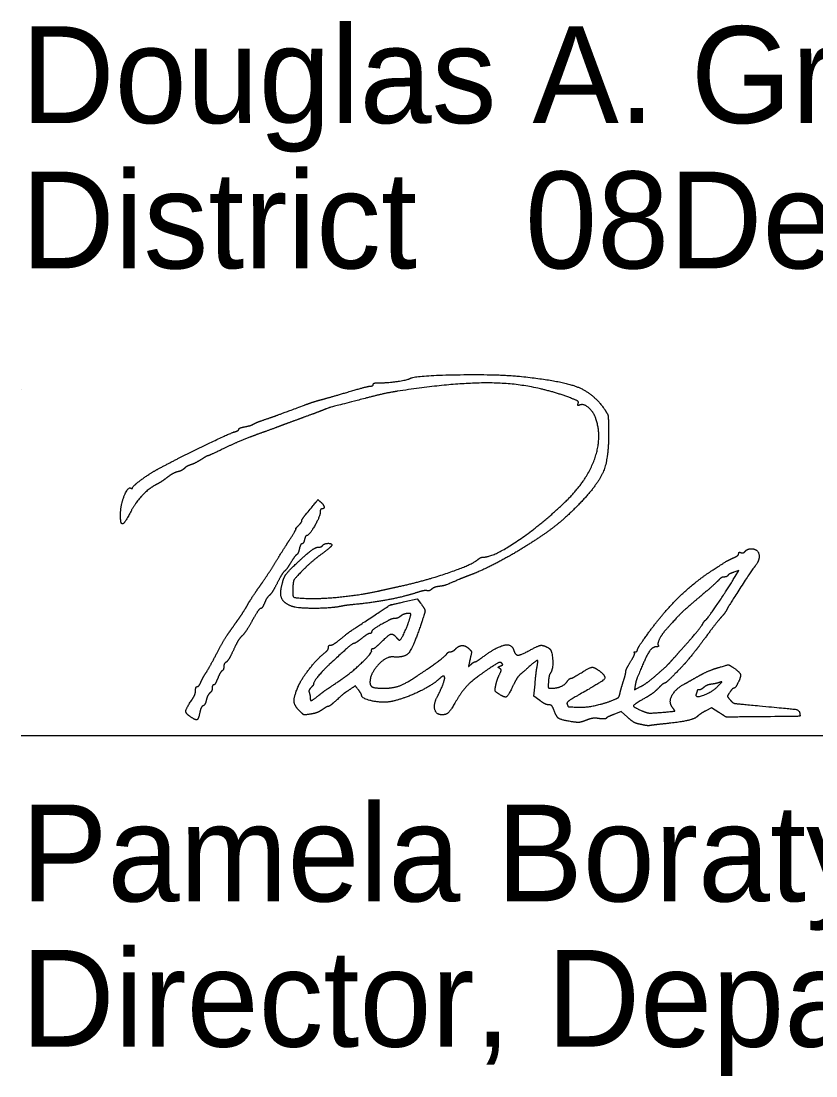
# Model space of a CAD drawing. Extents: x 0 to 34, y 0 to 22.
# Drawn here: x 24.5 to 25.648, y 7.199 to 8.723 of the extents above; entities that cross this region are included whole.
import ezdxf

# ---------------------------------------------------------------- set-up
doc = ezdxf.new("R2010")
doc.units = 0
doc.layers.add('SH_Data', color=7, linetype='Continuous')
doc.layers.add('SH_Text', color=7, linetype='Continuous')

msp = doc.modelspace()

# ---------------------------------------------------------------- linework, layer by layer
at = {"layer": 'SH_Data'}
for p, q in [((24.5, 8.191), (24.5, 8.191)), ((24.5, 7.691), (28, 7.691))]:
    msp.add_line(p, q, dxfattribs=at)
at = {"layer": 'SH_Text'}
for points in [[(25.5318, 7.9205), (25.5372, 7.9294), (25.5298, 7.9268)], [(25.0545, 7.8843), (25.0725, 7.8883), (25.0772, 7.8822)], [(25.2494, 7.7415), (25.2411, 7.7478), (25.2426, 7.7649)], [(25.3874, 7.7635), (25.3864, 7.757), (25.3951, 7.7614)], [(25.5083, 7.7242), (25.4976, 7.731), (25.4892, 7.7264)], [(25.3764, 7.7172), (25.3672, 7.7254), (25.3567, 7.7214)]]:
    msp.add_lwpolyline(points, dxfattribs=at)
for points in [[(25.0179, 8.2007), (25.0275, 8.2004), (25.0585, 8.2047), (25.0619, 8.2069)], [(25.0619, 8.2069), (25.0687, 8.2111), (25.1857, 8.2134), (25.2201, 8.21)], [(25.2201, 8.21), (25.2794, 8.2041), (25.3269, 8.1858), (25.3427, 8.1628)], [(24.9721, 8.1873), (24.9882, 8.192), (25.0031, 8.1959), (25.0051, 8.1959)], [(25.0437, 8.1884), (25.0345, 8.187), (25.0145, 8.1827), (24.9993, 8.1787)], [(25.0051, 8.1959), (25.0072, 8.1959), (25.0089, 8.1971), (25.0089, 8.1984)], [(25.0089, 8.1984), (25.0089, 8.1998), (25.0129, 8.2008), (25.0179, 8.2007)], [(25.2926, 8.1792), (25.242, 8.1982), (25.1341, 8.2022), (25.0437, 8.1884)], [(24.9093, 8.1683), (24.9172, 8.1713), (24.928, 8.1748), (24.9333, 8.1761)], [(24.9333, 8.1761), (24.9386, 8.1775), (24.9561, 8.1825), (24.9721, 8.1873)], [(24.9993, 8.1787), (24.9483, 8.1655), (24.944, 8.1643), (24.9333, 8.1599)], [(25.3049, 8.1706), (25.3059, 8.1731), (25.3024, 8.1755), (25.2926, 8.1792)], [(24.8529, 8.1477), (24.8676, 8.1528), (24.8741, 8.1552), (24.9093, 8.1683)], [(24.9333, 8.1599), (24.9307, 8.1589), (24.9204, 8.1551), (24.9105, 8.1515)], [(25.3073, 8.1685), (25.3047, 8.1675), (25.304, 8.1682), (25.3049, 8.1706)], [(25.3307, 8.1486), (25.3274, 8.1584), (25.313, 8.1707), (25.3073, 8.1685)], [(25.3427, 8.1628), (25.3476, 8.1555), (25.3486, 8.1512), (25.3489, 8.1333)], [(24.8349, 8.1405), (24.8362, 8.1415), (24.8443, 8.1448), (24.8529, 8.1477)], [(24.9105, 8.1515), (24.9006, 8.1479), (24.8855, 8.1423), (24.8769, 8.1391)], [(25.2852, 8.0274), (25.3161, 8.0568), (25.34, 8.1204), (25.3307, 8.1486)], [(24.6969, 8.0755), (24.7271, 8.0918), (24.8007, 8.1274), (24.8091, 8.1299)], [(24.8091, 8.1299), (24.8121, 8.1308), (24.8145, 8.1324), (24.8145, 8.1334)], [(24.8145, 8.1334), (24.8145, 8.1345), (24.8185, 8.1362), (24.8235, 8.1371)], [(24.8235, 8.1371), (24.8284, 8.138), (24.8336, 8.1396), (24.8349, 8.1405)], [(24.8769, 8.1391), (24.8683, 8.1358), (24.8521, 8.1299), (24.8409, 8.1259)], [(25.3489, 8.1333), (25.3496, 8.0926), (25.3335, 8.0529), (25.3041, 8.023)], [(24.8409, 8.1259), (24.8297, 8.1219), (24.8093, 8.1134), (24.7957, 8.1069)], [(24.7957, 8.1069), (24.782, 8.1004), (24.7704, 8.0951), (24.7698, 8.0951)], [(24.745, 8.082), (24.7418, 8.0809), (24.7376, 8.0786), (24.7358, 8.0768)], [(24.7598, 8.0895), (24.7549, 8.0864), (24.7482, 8.083), (24.745, 8.082)], [(24.7698, 8.0951), (24.7693, 8.0951), (24.7648, 8.0926), (24.7598, 8.0895)], [(24.6609, 8.0489), (24.6609, 8.0511), (24.6863, 8.0698), (24.6969, 8.0755)], [(24.7261, 8.072), (24.7226, 8.0711), (24.7159, 8.0675), (24.7113, 8.0639)], [(24.7358, 8.0768), (24.734, 8.075), (24.7297, 8.0728), (24.7261, 8.072)], [(24.6954, 8.0536), (24.685, 8.0482), (24.6651, 8.0274), (24.6589, 8.0153)], [(24.7113, 8.0639), (24.7067, 8.0603), (24.6995, 8.0557), (24.6954, 8.0536)], [(24.6437, 8.0111), (24.6438, 8.0242), (24.6545, 8.0508), (24.6586, 8.0483)], [(24.6586, 8.0483), (24.6599, 8.0475), (24.6609, 8.0478), (24.6609, 8.0489)], [(24.9111, 8.01), (24.9296, 8.0321), (24.9289, 8.0316), (24.933, 8.0282)], [(24.933, 8.0282), (24.9373, 8.0246), (24.9382, 8.0183), (24.9345, 8.0183)], [(25.1685, 7.9487), (25.1826, 7.9487), (25.2507, 7.9946), (25.2852, 8.0274)], [(25.3041, 8.023), (25.2855, 8.0041), (25.2531, 7.9792), (25.2226, 7.9603)], [(24.6451, 7.9973), (24.6443, 7.9981), (24.6437, 8.0043), (24.6437, 8.0111)], [(24.6589, 8.0153), (24.6522, 8.0024), (24.6469, 7.9955), (24.6451, 7.9973)], [(24.9057, 8.0013), (24.9057, 8.0025), (24.9081, 8.0064), (24.9111, 8.01)], [(24.9321, 8.0133), (24.9321, 8.0077), (24.9162, 7.9799), (24.913, 7.9799)], [(24.9345, 8.0183), (24.9332, 8.0183), (24.9321, 8.0161), (24.9321, 8.0133)], [(24.8881, 7.9739), (24.8937, 7.9825), (24.8977, 7.9895), (24.8971, 7.9895)], [(24.8971, 7.9895), (24.8966, 7.9895), (24.8983, 7.9917), (24.9009, 7.9943)], [(24.9009, 7.9943), (24.9035, 7.997), (24.9057, 8.0001), (24.9057, 8.0013)], [(24.913, 7.9799), (24.9119, 7.9799), (24.9103, 7.9772), (24.9095, 7.9739)], [(24.8661, 7.9389), (24.8727, 7.9495), (24.8826, 7.9653), (24.8881, 7.9739)], [(24.8973, 7.939), (24.913, 7.9536), (24.9258, 7.9631), (24.9297, 7.9631)], [(24.9021, 7.9608), (24.9012, 7.9568), (24.8995, 7.953), (24.8982, 7.9522)], [(24.9058, 7.9679), (24.9047, 7.9679), (24.903, 7.9647), (24.9021, 7.9608)], [(24.9095, 7.9739), (24.9087, 7.9706), (24.907, 7.9679), (24.9058, 7.9679)], [(24.9297, 7.9631), (24.9322, 7.9631), (24.9349, 7.9642), (24.9357, 7.9655)], [(24.9489, 7.9659), (24.9489, 7.9648), (24.9421, 7.9589), (24.9339, 7.9528)], [(24.9357, 7.9655), (24.9375, 7.9684), (24.9489, 7.9688), (24.9489, 7.9659)], [(25.2226, 7.9603), (25.2035, 7.9485), (25.1622, 7.9275), (25.1481, 7.9224)], [(25.5466, 7.9573), (25.5482, 7.9592), (25.5519, 7.9607), (25.5548, 7.9607)], [(25.5548, 7.9607), (25.5643, 7.9607), (25.568, 7.9447), (25.5606, 7.9357)], [(24.8982, 7.9522), (24.8969, 7.9514), (24.8931, 7.9462), (24.8897, 7.9407)], [(24.9339, 7.9528), (24.9256, 7.9467), (24.9131, 7.9358), (24.9061, 7.9287)], [(25.0485, 7.9068), (25.0854, 7.915), (25.1517, 7.9379), (25.1603, 7.9454)], [(25.1603, 7.9454), (25.1624, 7.9472), (25.1661, 7.9487), (25.1685, 7.9487)], [(25.5001, 7.9304), (25.5191, 7.9426), (25.5209, 7.9437), (25.5291, 7.9474)], [(25.5291, 7.9474), (25.5334, 7.9493), (25.5369, 7.9521), (25.5369, 7.9537)], [(25.5369, 7.9537), (25.5369, 7.9552), (25.5384, 7.9559), (25.5403, 7.9551)], [(25.5403, 7.9551), (25.5422, 7.9544), (25.545, 7.9554), (25.5466, 7.9573)], [(24.8443, 7.9059), (24.8497, 7.9134), (24.8595, 7.9282), (24.8661, 7.9389)], [(24.876, 7.9043), (24.8787, 7.9174), (24.8849, 7.9274), (24.8973, 7.939)], [(24.8897, 7.9407), (24.8863, 7.9352), (24.8822, 7.9296), (24.8806, 7.9283)], [(24.9061, 7.9287), (24.8954, 7.9177), (24.8932, 7.914), (24.8927, 7.9058)], [(25.4055, 7.8378), (25.4278, 7.8686), (25.4728, 7.9127), (25.5001, 7.9304)], [(25.5606, 7.9357), (25.5564, 7.9307), (25.5236, 7.8802), (25.5204, 7.8741)], [(24.8806, 7.9283), (24.8789, 7.927), (24.8742, 7.9194), (24.8702, 7.9114)], [(25.1325, 7.9162), (25.1154, 7.9088), (25.1105, 7.9071), (25.1039, 7.9063)], [(25.1481, 7.9224), (25.1435, 7.9207), (25.1364, 7.918), (25.1325, 7.9162)], [(25.507, 7.9145), (25.5043, 7.9116), (25.4918, 7.9005), (25.4793, 7.89)], [(25.489, 7.8575), (25.4918, 7.8595), (25.52, 7.901), (25.5318, 7.9205)], [(25.5158, 7.9199), (25.5136, 7.9199), (25.5097, 7.9175), (25.507, 7.9145)], [(25.5212, 7.9221), (25.5204, 7.9209), (25.518, 7.9199), (25.5158, 7.9199)], [(25.5298, 7.9268), (25.5258, 7.9254), (25.5219, 7.9233), (25.5212, 7.9221)], [(24.8276, 7.8803), (24.8315, 7.8869), (24.839, 7.8985), (24.8443, 7.9059)], [(24.8702, 7.9114), (24.8662, 7.9034), (24.8611, 7.8954), (24.859, 7.8936)], [(24.8913, 7.8775), (24.8809, 7.8814), (24.8737, 7.8938), (24.876, 7.9043)], [(24.8927, 7.9058), (24.8918, 7.8923), (24.8959, 7.8895), (24.9165, 7.8889)], [(24.9165, 7.8889), (24.9358, 7.8884), (24.9936, 7.8945), (25.0149, 7.8993)], [(25.0149, 7.8993), (25.0228, 7.9011), (25.0379, 7.9045), (25.0485, 7.9068)], [(25.0863, 7.9001), (25.0846, 7.9007), (25.0765, 7.899), (25.0683, 7.8963)], [(25.0931, 7.9022), (25.091, 7.9004), (25.0879, 7.8995), (25.0863, 7.9001)], [(25.1039, 7.9063), (25.1, 7.9059), (25.0952, 7.9041), (25.0931, 7.9022)], [(24.859, 7.8936), (24.8568, 7.8918), (24.8535, 7.8867), (24.8517, 7.8823)], [(25.0683, 7.8963), (25.0518, 7.891), (25.0067, 7.8826), (24.9829, 7.8803)], [(25.0005, 7.8579), (25.0322, 7.8789), (25.0335, 7.8796), (25.0545, 7.8843)], [(25.4793, 7.89), (25.4597, 7.8734), (25.448, 7.862), (25.4313, 7.8432)], [(24.8146, 7.8597), (24.8179, 7.8645), (24.8238, 7.8737), (24.8276, 7.8803)], [(24.846, 7.8743), (24.8447, 7.8743), (24.8393, 7.8664), (24.8339, 7.8568)], [(24.8517, 7.8823), (24.8498, 7.8779), (24.8473, 7.8743), (24.846, 7.8743)], [(24.9625, 7.8776), (24.9488, 7.8746), (24.8993, 7.8745), (24.8913, 7.8775)], [(24.9829, 7.8803), (24.9746, 7.8795), (24.9654, 7.8783), (24.9625, 7.8776)], [(25.0772, 7.8822), (25.0838, 7.8734), (25.0836, 7.8685), (25.0759, 7.846)], [(25.5204, 7.8741), (25.5187, 7.8706), (25.5148, 7.8652), (25.5118, 7.8619)], [(24.801, 7.8405), (24.8051, 7.8463), (24.8112, 7.8549), (24.8146, 7.8597)], [(24.8339, 7.8568), (24.8286, 7.8471), (24.8219, 7.8371), (24.8191, 7.8346)], [(24.9613, 7.83), (24.975, 7.841), (24.973, 7.8396), (25.0005, 7.8579)], [(25.0302, 7.8568), (25.0158, 7.8489), (25.0065, 7.8425), (25.0065, 7.8405)], [(25.0399, 7.8599), (25.0377, 7.8599), (25.0333, 7.8585), (25.0302, 7.8568)], [(25.0486, 7.8635), (25.0461, 7.8615), (25.0421, 7.8599), (25.0399, 7.8599)], [(25.0471, 7.8287), (25.0489, 7.8287), (25.0587, 7.8499), (25.0618, 7.8605)], [(25.0585, 7.8671), (25.0557, 7.867), (25.0512, 7.8654), (25.0486, 7.8635)], [(25.0618, 7.8605), (25.0635, 7.8663), (25.0631, 7.8671), (25.0585, 7.8671)], [(25.4538, 7.8146), (25.4691, 7.8317), (25.4827, 7.8481), (25.4851, 7.8524)], [(25.4851, 7.8524), (25.4863, 7.8546), (25.4881, 7.8569), (25.489, 7.8575)], [(25.5118, 7.8619), (25.5088, 7.8587), (25.4999, 7.8474), (25.492, 7.8367)], [(24.7821, 7.8083), (24.7884, 7.8202), (24.7969, 7.8347), (24.801, 7.8405)], [(25.0038, 7.8383), (25.0024, 7.8383), (24.9971, 7.8351), (24.9921, 7.8311)], [(25.0065, 7.8405), (25.0065, 7.8393), (25.0053, 7.8383), (25.0038, 7.8383)], [(25.0209, 7.8263), (25.031, 7.8365), (25.0376, 7.8383), (25.0425, 7.8323)], [(25.0759, 7.846), (25.0656, 7.8161), (25.0537, 7.803), (25.0377, 7.8044)], [(25.3905, 7.8145), (25.3905, 7.8159), (25.3972, 7.8264), (25.4055, 7.8378)], [(25.4313, 7.8432), (25.4255, 7.8366), (25.4192, 7.8237), (25.4206, 7.8213)], [(24.8191, 7.8346), (24.8162, 7.832), (24.8107, 7.8229), (24.8068, 7.8143)], [(24.981, 7.8239), (24.9791, 7.8239), (24.9706, 7.8167), (24.9453, 7.7934)], [(24.9475, 7.8215), (24.9493, 7.8215), (24.9555, 7.8253), (24.9613, 7.83)], [(24.9921, 7.8311), (24.9871, 7.8272), (24.9821, 7.8239), (24.981, 7.8239)], [(25.0089, 7.8167), (25.0102, 7.8167), (25.0156, 7.8211), (25.0209, 7.8263)], [(25.0425, 7.8323), (25.0441, 7.8304), (25.0462, 7.8287), (25.0471, 7.8287)], [(25.1657, 7.8033), (25.1859, 7.8184), (25.2086, 7.824), (25.2116, 7.8146)], [(25.492, 7.8367), (25.4841, 7.8261), (25.4765, 7.8159), (25.475, 7.814)], [(24.7667, 7.7807), (24.7689, 7.784), (24.7759, 7.7965), (24.7821, 7.8083)], [(24.8068, 7.8143), (24.8029, 7.8058), (24.7981, 7.7979), (24.7963, 7.7968)], [(24.9006, 7.7621), (24.9051, 7.7725), (24.9283, 7.802), (24.9387, 7.8103)], [(24.9387, 7.8103), (24.9417, 7.8127), (24.9441, 7.8162), (24.9441, 7.8181)], [(24.9441, 7.8181), (24.9441, 7.82), (24.9456, 7.8215), (24.9475, 7.8215)], [(24.9604, 7.7702), (24.976, 7.7806), (25.0065, 7.8093), (25.0065, 7.8136)], [(25.0065, 7.8136), (25.0065, 7.8153), (25.0076, 7.8167), (25.0089, 7.8167)], [(25.0725, 7.7771), (25.0911, 7.7894), (25.1135, 7.8061), (25.1152, 7.8089)], [(25.1152, 7.8089), (25.1163, 7.8106), (25.1186, 7.8119), (25.1204, 7.8119)], [(25.1204, 7.8119), (25.1223, 7.8119), (25.1255, 7.8137), (25.1277, 7.8158)], [(25.1277, 7.8158), (25.1326, 7.8208), (25.1426, 7.8209), (25.1475, 7.8159)], [(25.1475, 7.8159), (25.1507, 7.8128), (25.1509, 7.8103), (25.1488, 7.8011)], [(25.2116, 7.8146), (25.214, 7.807), (25.2221, 7.8069), (25.2354, 7.8142)], [(25.2354, 7.8142), (25.2474, 7.8208), (25.2546, 7.8216), (25.2628, 7.817)], [(25.2628, 7.817), (25.2672, 7.8145), (25.2689, 7.7865), (25.265, 7.7813)], [(25.3807, 7.7976), (25.3846, 7.8039), (25.3871, 7.8097), (25.3863, 7.8105)], [(25.3863, 7.8105), (25.3855, 7.8113), (25.3862, 7.8119), (25.3877, 7.8119)], [(25.3877, 7.8119), (25.3892, 7.8119), (25.3905, 7.8131), (25.3905, 7.8145)], [(25.4184, 7.8191), (25.412, 7.8191), (25.4025, 7.804), (25.3904, 7.7747)], [(25.4206, 7.8213), (25.4214, 7.8201), (25.4204, 7.8191), (25.4184, 7.8191)], [(25.4382, 7.7971), (25.4413, 7.8006), (25.4484, 7.8085), (25.4538, 7.8146)], [(25.475, 7.814), (25.4617, 7.7976), (25.4572, 7.7925), (25.4453, 7.7803)], [(24.7963, 7.7968), (24.7944, 7.7958), (24.7929, 7.7929), (24.7929, 7.7904)], [(24.9453, 7.7934), (24.9362, 7.785), (24.9225, 7.768), (24.9225, 7.765)], [(25.0377, 7.8044), (25.0273, 7.8053), (25.0041, 7.7799), (25.0041, 7.7676)], [(25.1488, 7.8011), (25.1465, 7.7909), (25.1466, 7.7904), (25.1504, 7.7939)], [(25.1504, 7.7939), (25.1526, 7.7959), (25.1553, 7.7975), (25.1562, 7.7975)], [(25.1562, 7.7975), (25.1572, 7.7975), (25.1615, 7.8001), (25.1657, 7.8033)], [(25.1943, 7.7955), (25.1925, 7.7973), (25.1866, 7.7945), (25.1741, 7.786)], [(25.1915, 7.7878), (25.1893, 7.7892), (25.1896, 7.7901), (25.1927, 7.7913)], [(25.1927, 7.7913), (25.1957, 7.7924), (25.1962, 7.7936), (25.1943, 7.7955)], [(25.2354, 7.7914), (25.2195, 7.7774), (25.2158, 7.773), (25.2103, 7.7616)], [(25.2455, 7.7897), (25.2474, 7.7992), (25.2447, 7.7996), (25.2354, 7.7914)], [(25.3737, 7.7829), (25.3737, 7.7847), (25.3769, 7.7914), (25.3807, 7.7976)], [(25.4181, 7.7783), (25.426, 7.7851), (25.4351, 7.7936), (25.4382, 7.7971)], [(25.5074, 7.789), (25.5215, 7.7932), (25.5226, 7.7932), (25.5285, 7.7894)], [(24.7598, 7.7681), (24.7614, 7.7718), (24.7645, 7.7774), (24.7667, 7.7807)], [(24.7904, 7.7843), (24.789, 7.7834), (24.7862, 7.7785), (24.7841, 7.7733)], [(24.7929, 7.7904), (24.7929, 7.7879), (24.7918, 7.7851), (24.7904, 7.7843)], [(25.024, 7.7591), (25.0371, 7.7591), (25.0562, 7.7662), (25.0725, 7.7771)], [(25.1121, 7.7738), (25.1121, 7.7769), (25.1081, 7.7764), (25.1045, 7.7729)], [(25.1741, 7.786), (25.1544, 7.7726), (25.1372, 7.7555), (25.1289, 7.7411)], [(25.1857, 7.7623), (25.1865, 7.7665), (25.1888, 7.7736), (25.1908, 7.778)], [(25.1908, 7.778), (25.1937, 7.7842), (25.1938, 7.7864), (25.1915, 7.7878)], [(25.2426, 7.7649), (25.2434, 7.7743), (25.2447, 7.7854), (25.2455, 7.7897)], [(25.265, 7.7813), (25.2637, 7.7797), (25.2624, 7.774), (25.262, 7.7687)], [(25.2945, 7.7735), (25.2957, 7.7735), (25.3018, 7.7768), (25.3081, 7.7807)], [(25.3363, 7.7837), (25.346, 7.7761), (25.3391, 7.7682), (25.3076, 7.7505)], [(25.3081, 7.7807), (25.321, 7.789), (25.3286, 7.7898), (25.3363, 7.7837)], [(25.3702, 7.7687), (25.3721, 7.7747), (25.3737, 7.781), (25.3737, 7.7829)], [(25.3951, 7.7614), (25.3998, 7.7639), (25.4102, 7.7715), (25.4181, 7.7783)], [(25.4453, 7.7803), (25.4378, 7.7726), (25.4308, 7.7663), (25.4297, 7.7663)], [(25.4585, 7.7653), (25.4614, 7.7668), (25.4702, 7.7718), (25.4781, 7.7763)], [(25.4781, 7.7763), (25.486, 7.7808), (25.4992, 7.7865), (25.5074, 7.789)], [(25.5285, 7.7894), (25.5381, 7.7831), (25.5405, 7.7757), (25.5359, 7.7667)], [(24.7521, 7.7559), (24.7521, 7.759), (24.7532, 7.7615), (24.7545, 7.7615)], [(24.7545, 7.7615), (24.7559, 7.7615), (24.7583, 7.7645), (24.7598, 7.7681)], [(24.7782, 7.7639), (24.7771, 7.7639), (24.7761, 7.7619), (24.7761, 7.7594)], [(24.7841, 7.7733), (24.7821, 7.7682), (24.7794, 7.7639), (24.7782, 7.7639)], [(24.9023, 7.7264), (24.8947, 7.734), (24.8941, 7.7468), (24.9006, 7.7621)], [(24.9225, 7.765), (24.9225, 7.7642), (24.9208, 7.7619), (24.9188, 7.7599)], [(24.9289, 7.7478), (24.9364, 7.7539), (24.9417, 7.7576), (24.9604, 7.7702)], [(24.9875, 7.7566), (24.983, 7.7624), (24.983, 7.7624), (24.9762, 7.758)], [(25.0041, 7.7676), (25.0041, 7.7625), (25.0119, 7.7591), (25.024, 7.7591)], [(25.1045, 7.7729), (25.0949, 7.7638), (25.0562, 7.745), (25.0377, 7.7405)], [(25.1015, 7.7471), (25.1056, 7.7548), (25.1121, 7.7711), (25.1121, 7.7738)], [(25.1903, 7.7508), (25.1853, 7.7541), (25.1845, 7.7561), (25.1857, 7.7623)], [(25.2103, 7.7616), (25.2036, 7.7479), (25.1988, 7.7453), (25.1903, 7.7508)], [(25.262, 7.7687), (25.2615, 7.7612), (25.2622, 7.7591), (25.2654, 7.7591)], [(25.2654, 7.7591), (25.2737, 7.7591), (25.2857, 7.764), (25.289, 7.7687)], [(25.289, 7.7687), (25.2908, 7.7713), (25.2933, 7.7735), (25.2945, 7.7735)], [(25.3654, 7.7517), (25.3661, 7.7551), (25.3683, 7.7628), (25.3702, 7.7687)], [(25.3904, 7.7747), (25.3893, 7.7721), (25.388, 7.767), (25.3874, 7.7635)], [(25.4297, 7.7663), (25.4286, 7.7663), (25.4247, 7.7632), (25.4211, 7.7594)], [(25.4415, 7.7309), (25.4354, 7.7383), (25.4452, 7.7581), (25.4585, 7.7653)], [(25.4755, 7.751), (25.473, 7.7445), (25.4984, 7.7534), (25.5069, 7.7621)], [(25.4975, 7.7649), (25.4936, 7.7644), (25.4887, 7.7623), (25.4865, 7.7603)], [(25.5093, 7.7676), (25.5067, 7.7666), (25.5013, 7.7654), (25.4975, 7.7649)], [(25.5069, 7.7621), (25.5124, 7.7676), (25.513, 7.769), (25.5093, 7.7676)], [(25.5359, 7.7667), (25.5337, 7.7625), (25.531, 7.7591), (25.5299, 7.7591)], [(24.7463, 7.7416), (24.7495, 7.7464), (24.7521, 7.7528), (24.7521, 7.7559)], [(24.7727, 7.7521), (24.7708, 7.7505), (24.7685, 7.746), (24.7676, 7.742)], [(24.7761, 7.7594), (24.7761, 7.757), (24.7745, 7.7536), (24.7727, 7.7521)], [(24.9188, 7.7599), (24.9167, 7.7578), (24.9156, 7.7546), (24.9164, 7.7526)], [(24.9164, 7.7526), (24.9171, 7.7507), (24.9177, 7.7476), (24.9177, 7.7457)], [(24.9177, 7.7457), (24.9177, 7.7409), (24.9211, 7.7415), (24.9289, 7.7478)], [(24.9762, 7.758), (24.968, 7.7526), (24.9654, 7.7506), (24.9542, 7.7405)], [(24.992, 7.7492), (24.992, 7.75), (24.99, 7.7534), (24.9875, 7.7566)], [(25.0377, 7.7405), (25.0248, 7.7374), (24.9922, 7.7436), (24.992, 7.7492)], [(25.1082, 7.7207), (25.0998, 7.7207), (25.0958, 7.7365), (25.1015, 7.7471)], [(25.3076, 7.7505), (25.2943, 7.743), (25.2881, 7.7382), (25.289, 7.736)], [(25.3527, 7.741), (25.3615, 7.7444), (25.3645, 7.7469), (25.3654, 7.7517)], [(25.4031, 7.7458), (25.3852, 7.7354), (25.3842, 7.7321), (25.3971, 7.7266)], [(25.4211, 7.7594), (25.4175, 7.7556), (25.4094, 7.7494), (25.4031, 7.7458)], [(25.4769, 7.7557), (25.4769, 7.7552), (25.4763, 7.7531), (25.4755, 7.751)], [(25.4797, 7.7567), (25.4782, 7.7567), (25.4769, 7.7563), (25.4769, 7.7557)], [(25.4865, 7.7603), (25.4843, 7.7584), (25.4813, 7.7567), (25.4797, 7.7567)], [(25.524, 7.7533), (25.5205, 7.748), (25.5206, 7.7471), (25.5244, 7.7424)], [(25.5299, 7.7591), (25.5288, 7.7591), (25.5261, 7.7565), (25.524, 7.7533)], [(24.7446, 7.7179), (24.7376, 7.7228), (24.7381, 7.7295), (24.7463, 7.7416)], [(24.7629, 7.7336), (24.7612, 7.7329), (24.7591, 7.7288), (24.7583, 7.7244)], [(24.7676, 7.742), (24.7668, 7.7381), (24.7646, 7.7343), (24.7629, 7.7336)], [(24.9435, 7.7327), (24.9424, 7.7327), (24.9386, 7.7306), (24.935, 7.728)], [(24.9542, 7.7405), (24.9494, 7.7362), (24.9446, 7.7327), (24.9435, 7.7327)], [(25.1289, 7.7411), (25.1207, 7.727), (25.1143, 7.7207), (25.1082, 7.7207)], [(25.2624, 7.7351), (25.2599, 7.7351), (25.254, 7.738), (25.2494, 7.7415)], [(25.27, 7.7273), (25.2681, 7.7325), (25.2656, 7.7351), (25.2624, 7.7351)], [(25.289, 7.736), (25.2903, 7.7326), (25.291, 7.7324), (25.3029, 7.7317)], [(25.3029, 7.7317), (25.3134, 7.7311), (25.3396, 7.736), (25.3527, 7.741)], [(25.4239, 7.7241), (25.4434, 7.7257), (25.4452, 7.7264), (25.4415, 7.7309)], [(25.5244, 7.7424), (25.528, 7.7379), (25.533, 7.7368), (25.5669, 7.7337)], [(25.5669, 7.7337), (25.616, 7.7292), (25.6243, 7.7276), (25.6252, 7.7228)], [(24.7583, 7.7244), (24.7564, 7.7146), (24.7522, 7.7127), (24.7446, 7.7179)], [(24.9185, 7.7217), (24.9098, 7.7204), (24.9076, 7.721), (24.9023, 7.7264)], [(24.935, 7.728), (24.9314, 7.7254), (24.924, 7.7226), (24.9185, 7.7217)], [(25.2953, 7.7108), (25.2803, 7.7132), (25.2735, 7.7177), (25.27, 7.7273)], [(25.3353, 7.7153), (25.3295, 7.7161), (25.3222, 7.7151), (25.3164, 7.7128)], [(25.3454, 7.7156), (25.345, 7.7148), (25.3404, 7.7146), (25.3353, 7.7153)], [(25.3567, 7.7214), (25.3509, 7.7191), (25.3458, 7.7165), (25.3454, 7.7156)], [(25.391, 7.7077), (25.388, 7.7083), (25.3814, 7.7126), (25.3764, 7.7172)], [(25.3971, 7.7266), (25.4039, 7.7236), (25.4104, 7.723), (25.4239, 7.7241)], [(25.4775, 7.7186), (25.4738, 7.7149), (25.4523, 7.71), (25.4289, 7.7076)], [(25.4892, 7.7264), (25.4846, 7.724), (25.4794, 7.7204), (25.4775, 7.7186)], [(25.5549, 7.7177), (25.5192, 7.7174), (25.5188, 7.7174), (25.5083, 7.7242)], [(25.6252, 7.7228), (25.626, 7.7186), (25.624, 7.7185), (25.5549, 7.7177)], [(25.3164, 7.7128), (25.3094, 7.71), (25.3039, 7.7094), (25.2953, 7.7108)], [(25.4013, 7.7055), (25.3987, 7.7061), (25.394, 7.7071), (25.391, 7.7077)], [(25.4097, 7.7053), (25.4077, 7.7049), (25.4039, 7.705), (25.4013, 7.7055)], [(25.4289, 7.7076), (25.4203, 7.7067), (25.4117, 7.7057), (25.4097, 7.7053)]]:
    msp.add_open_spline(points, degree=2, dxfattribs=at)

# ---------------------------------------------------------------- texts
for s, p in [('Douglas A. Gruver, P.E.', (24.5, 8.576)), ('District       Deputy Director', (24.5, 8.366)), ('              08', (24.5, 8.366)), ('Pamela Boratyn', (24.5, 7.451)), ('Director, Department of Transportation', (24.5, 7.241))]:
    msp.add_text(s, height=0.14, dxfattribs=at).set_placement(p)

doc.saveas('drawing.dxf')
